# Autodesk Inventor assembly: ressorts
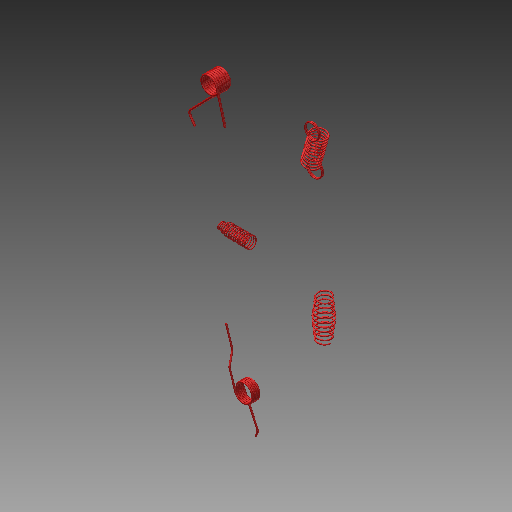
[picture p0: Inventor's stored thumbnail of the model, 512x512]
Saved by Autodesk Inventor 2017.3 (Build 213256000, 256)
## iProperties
Created: 2011-02
Part Number: ressorts
Material: Générique
Document SubType Name: Assembly
Designer: ficho
Author: ficho
Sending System: SolidWorks 2009
Last Author: christophe
Last Saved: 2011-02-11
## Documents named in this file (6)
- G:\travail\année 2019-2020\réforme\toussaint\Serrure biométrique SET\Documentations_pedagogique\Modelisation_Solidworks\ressorts.iam
- G:\travail\année 2019-2020\réforme\toussaint\Serrure biométrique SET\Documentations_pedagogique\Modelisation_Solidworks\ressort2.ipt
- G:\travail\année 2019-2020\réforme\toussaint\Serrure biométrique SET\Documentations_pedagogique\Modelisation_Solidworks\ressort3 position fermée.ipt
- G:\travail\année 2019-2020\réforme\toussaint\Serrure biométrique SET\Documentations_pedagogique\Modelisation_Solidworks\ressort6 position fermée.ipt
- G:\travail\année 2019-2020\réforme\toussaint\Serrure biométrique SET\Documentations_pedagogique\Modelisation_Solidworks\ressort4 position fermée.ipt
- G:\travail\année 2019-2020\réforme\toussaint\Serrure biométrique SET\Documentations_pedagogique\Modelisation_Solidworks\ressort 5 position fermée.ipt
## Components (5 placed, 5 different names)
1. ressort2:2
2. ressort3 position fermée:1
3. ressort6 position fermée:2
4. ressort4 position fermée:1
5. ressort 5 position fermée:1
